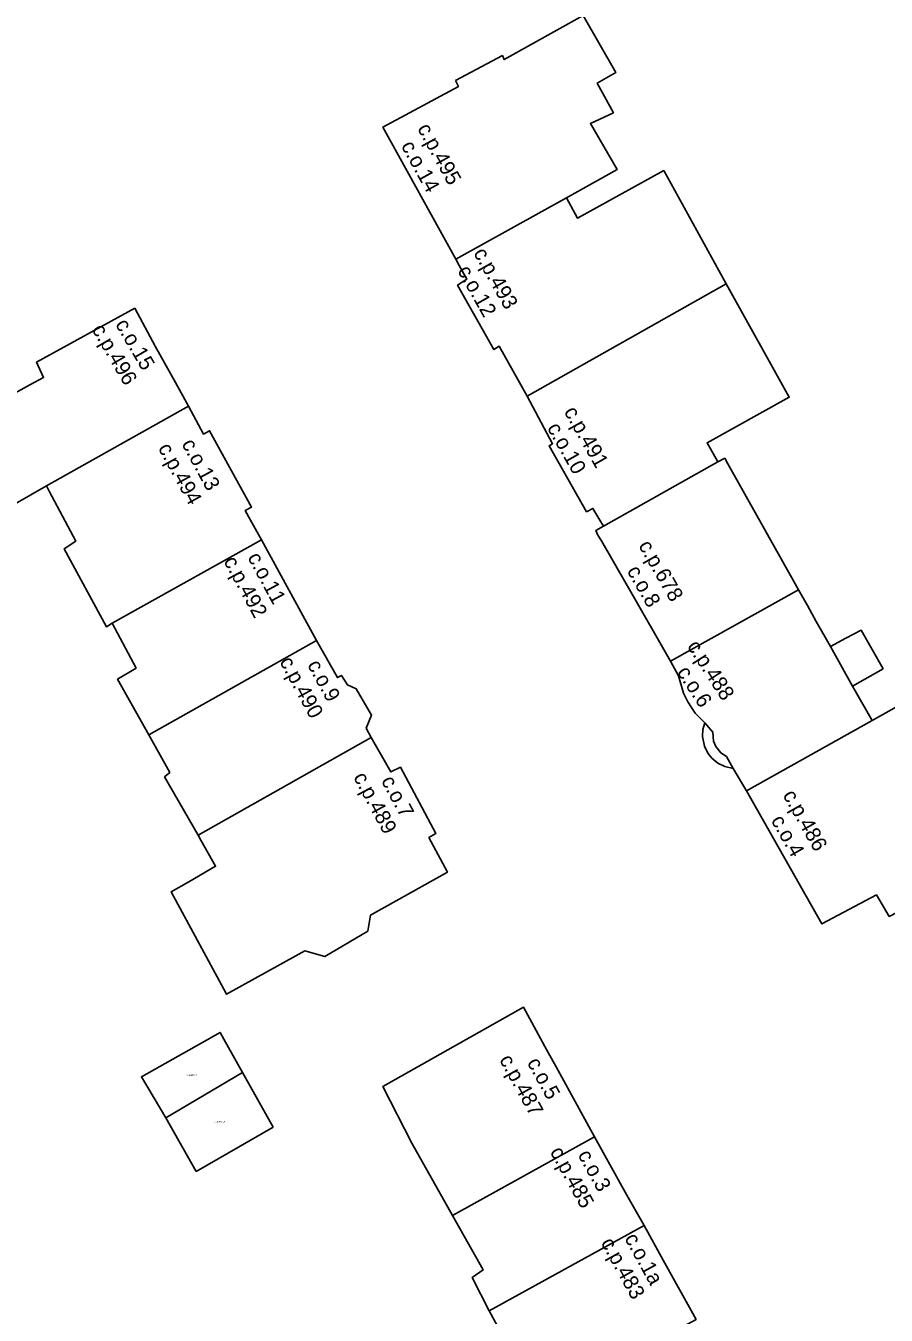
# Model space of a CAD drawing. Extents: x -600391 to -599491, y -1160176 to -1159402.
# Drawn here: x -600213.3 to -600156.5, y -1160026.2 to -1159941 of the extents above; entities that cross this region are included whole.
import ezdxf

# ---------------------------------------------------------------- set-up
doc = ezdxf.new("R2010")
doc.units = 0
for name, color, linetype in [('Level 10', 7, 'Continuous'), ('Level 12', 7, 'Continuous'), ('Level 25', 7, 'Continuous'), ('Level 61', 7, 'Continuous'), ('Level 62', 7, 'Continuous')]:
    doc.layers.add(name, color=color, linetype=linetype)

msp = doc.modelspace()

# ---------------------------------------------------------------- linework, layer by layer
at = {"layer": 'Level 61'}
for points in [[(-600181.7, -1159943.27), (-600176.48, -1159940.35)], [(-600176.48, -1159940.35), (-600174.33, -1159944.13)], [(-600184.92, -1159944.66), (-600181.82, -1159943.01)], [(-600181.82, -1159943.01), (-600181.7, -1159943.27)], [(-600184.72, -1159945.04), (-600184.92, -1159944.66)], [(-600174.33, -1159944.13), (-600175.55, -1159944.82)], [(-600189.71, -1159947.73), (-600184.72, -1159945.04)], [(-600175.55, -1159944.82), (-600174.49, -1159946.78)], [(-600174.49, -1159946.78), (-600176.01, -1159947.5)], [(-600184.9, -1159956.46), (-600189.71, -1159947.73)], [(-600176.01, -1159947.5), (-600174.24, -1159950.54)], [(-600174.24, -1159950.54), (-600177.59, -1159952.4)], [(-600176.86, -1159953.74), (-600171.16, -1159950.6)], [(-600171.16, -1159950.6), (-600167.05, -1159958.08)], [(-600177.59, -1159952.4), (-600184.9, -1159956.46)], [(-600184.9, -1159956.46), (-600177.59, -1159952.4)], [(-600177.59, -1159952.4), (-600176.86, -1159953.74)], [(-600184.67, -1159956.87), (-600184.9, -1159956.46)], [(-600184.17, -1159957.78), (-600184.67, -1159956.87)], [(-600184.78, -1159958.16), (-600184.17, -1159957.78)], [(-600182.38, -1159962.42), (-600184.78, -1159958.16)], [(-600167.05, -1159958.08), (-600180.17, -1159965.49)], [(-600180.17, -1159965.49), (-600167.05, -1159958.08)], [(-600167.05, -1159958.08), (-600162.88, -1159965.57)], [(-600212.57, -1159963.25), (-600206.09, -1159959.69)], [(-600206.09, -1159959.69), (-600204.75, -1159962.19)], [(-600204.75, -1159962.19), (-600203.41, -1159964.59)], [(-600182.03, -1159962.2), (-600182.38, -1159962.42)], [(-600180.17, -1159965.49), (-600182.03, -1159962.2)], [(-600212.11, -1159964.26), (-600212.57, -1159963.25)], [(-600213.02, -1159964.76), (-600212.11, -1159964.26)], [(-600215.57, -1159966.17), (-600213.02, -1159964.76)], [(-600203.41, -1159964.59), (-600202.55, -1159966.16)], [(-600178.5, -1159968.64), (-600180.17, -1159965.49)], [(-600162.88, -1159965.57), (-600168.3, -1159968.58)], [(-600211.91, -1159971.43), (-600202.55, -1159966.16)], [(-600202.55, -1159966.16), (-600211.91, -1159971.43)], [(-600202.55, -1159966.16), (-600201.55, -1159968)], [(-600201.55, -1159968), (-600201.15, -1159967.78)], [(-600201.15, -1159967.78), (-600198.39, -1159972.83)], [(-600178.73, -1159968.77), (-600178.5, -1159968.64)], [(-600168.3, -1159968.58), (-600167.59, -1159969.84)], [(-600176.26, -1159973.13), (-600178.73, -1159968.77)], [(-600175.15, -1159974.08), (-600167.59, -1159969.84)], [(-600167.59, -1159969.84), (-600175.15, -1159974.08)], [(-600167.59, -1159969.84), (-600167.14, -1159969.6)], [(-600167.14, -1159969.6), (-600166.94, -1159969.96)], [(-600166.94, -1159969.96), (-600162.6, -1159977.69)], [(-600211.91, -1159971.43), (-600213.99, -1159972.6)], [(-600211.73, -1159971.78), (-600211.91, -1159971.43)], [(-600209.99, -1159975.07), (-600211.73, -1159971.78)], [(-600198.39, -1159972.83), (-600198.79, -1159973.05)], [(-600198.79, -1159973.05), (-600198.44, -1159973.69)], [(-600198.44, -1159973.69), (-600197.72, -1159974.99)], [(-600175.84, -1159972.91), (-600176.26, -1159973.13)], [(-600175.39, -1159973.68), (-600175.84, -1159972.91)], [(-600175.15, -1159974.08), (-600175.39, -1159973.68)], [(-600175.65, -1159974.37), (-600175.15, -1159974.08)], [(-600175.51, -1159974.68), (-600175.65, -1159974.37)], [(-600210.75, -1159975.58), (-600209.99, -1159975.07)], [(-600197.72, -1159974.99), (-600207.58, -1159980.5)], [(-600207.58, -1159980.5), (-600197.72, -1159974.99)], [(-600197.72, -1159974.99), (-600194.09, -1159981.64)], [(-600175.27, -1159975.05), (-600175.51, -1159974.68)], [(-600173.64, -1159977.9), (-600175.27, -1159975.05)], [(-600207.96, -1159980.73), (-600210.75, -1159975.58)], [(-600173.42, -1159978.27), (-600173.64, -1159977.9)], [(-600162.6, -1159977.69), (-600162.26, -1159978.29)], [(-600170.72, -1159982.99), (-600173.42, -1159978.27)], [(-600170.72, -1159982.99), (-600162.26, -1159978.29)], [(-600162.26, -1159978.29), (-600170.72, -1159982.99)], [(-600162.26, -1159978.29), (-600161.68, -1159979.33)], [(-600161.68, -1159979.33), (-600161.09, -1159980.38)], [(-600207.58, -1159980.5), (-600207.96, -1159980.73)], [(-600206, -1159983.45), (-600207.58, -1159980.5)], [(-600161.09, -1159980.38), (-600160.15, -1159982.04)], [(-600159.13, -1159981.49), (-600158.13, -1159980.95)], [(-600158.13, -1159980.95), (-600156.68, -1159983.5)], [(-600205.17, -1159987.86), (-600194.09, -1159981.64)], [(-600194.09, -1159981.64), (-600205.17, -1159987.86)], [(-600194.09, -1159981.64), (-600192.71, -1159984.08)], [(-600160.15, -1159982.04), (-600159.13, -1159981.49)], [(-600158.7, -1159984.64), (-600160.15, -1159982.04)], [(-600160.15, -1159982.04), (-600158.7, -1159984.64)], [(-600170.18, -1159983.97), (-600170.72, -1159982.99)], [(-600207.22, -1159984.19), (-600206, -1159983.45)], [(-600192.71, -1159984.08), (-600192.45, -1159983.94)], [(-600192.45, -1159983.94), (-600192.04, -1159984.57)], [(-600169.85, -1159985.11), (-600170.18, -1159983.97)], [(-600156.68, -1159983.5), (-600158.7, -1159984.64)], [(-600205.17, -1159987.86), (-600207.22, -1159984.19)], [(-600192.04, -1159984.57), (-600191.47, -1159984.83)], [(-600158.7, -1159984.64), (-600157.41, -1159986.92)], [(-600191.47, -1159984.83), (-600190.46, -1159986.56)], [(-600169.57, -1159985.69), (-600169.85, -1159985.11)], [(-600169.09, -1159986.43), (-600169.57, -1159985.69)], [(-600168.45, -1159987.06), (-600169.09, -1159986.43)], [(-600157.41, -1159986.92), (-600155.25, -1159985.7)], [(-600190.46, -1159986.56), (-600190.82, -1159987.42)], [(-600168.59, -1159987.52), (-600168.45, -1159987.06)], [(-600167.93, -1159987.69), (-600168.45, -1159987.06)], [(-600168.45, -1159987.06), (-600167.93, -1159987.69)], [(-600157.41, -1159986.92), (-600165.71, -1159991.56)], [(-600165.71, -1159991.56), (-600157.41, -1159986.92)], [(-600203.78, -1159990.35), (-600205.17, -1159987.86)], [(-600190.48, -1159988.03), (-600201.9, -1159994.48)], [(-600201.9, -1159994.48), (-600190.48, -1159988.03)], [(-600190.82, -1159987.42), (-600190.48, -1159988.03)], [(-600190.48, -1159988.03), (-600189.19, -1159990.31)], [(-600168.6, -1159987.98), (-600168.59, -1159987.52)], [(-600168.47, -1159988.62), (-600168.6, -1159987.98)], [(-600167.87, -1159988.29), (-600167.93, -1159987.69)], [(-600167.93, -1159987.69), (-600167.87, -1159988.29)], [(-600168.28, -1159989.03), (-600168.47, -1159988.62)], [(-600168.19, -1159989.16), (-600168.28, -1159989.03)], [(-600167.73, -1159988.64), (-600167.87, -1159988.29)], [(-600167.87, -1159988.29), (-600167.73, -1159988.64)], [(-600167.4, -1159989.06), (-600167.73, -1159988.64)], [(-600167.73, -1159988.64), (-600167.4, -1159989.06)], [(-600167.03, -1159989.3), (-600167.4, -1159989.06)], [(-600167.4, -1159989.06), (-600167.03, -1159989.3)], [(-600167.99, -1159989.4), (-600168.19, -1159989.16)], [(-600167.59, -1159989.73), (-600167.99, -1159989.4)], [(-600167.14, -1159989.95), (-600167.59, -1159989.73)], [(-600166.59, -1159990.08), (-600167.03, -1159989.3)], [(-600167.03, -1159989.3), (-600166.59, -1159990.08)], [(-600204.12, -1159990.64), (-600203.78, -1159990.35)], [(-600201.9, -1159994.48), (-600204.12, -1159990.64)], [(-600189.19, -1159990.31), (-600188.55, -1159990)], [(-600188.55, -1159990), (-600186.21, -1159994.37)], [(-600166.59, -1159990.08), (-600167.14, -1159989.95)], [(-600165.71, -1159991.56), (-600166.59, -1159990.08)], [(-600160.72, -1160000.35), (-600165.71, -1159991.56)], [(-600201.72, -1159994.81), (-600201.9, -1159994.48)], [(-600200.75, -1159996.54), (-600201.72, -1159994.81)], [(-600186.21, -1159994.37), (-600186.67, -1159994.65)], [(-600186.67, -1159994.65), (-600185.45, -1159996.93)], [(-600202.52, -1159997.56), (-600200.75, -1159996.54)], [(-600203.69, -1159998.23), (-600202.52, -1159997.56)], [(-600185.45, -1159996.93), (-600190.52, -1159999.77)], [(-600200.21, -1160004.66), (-600203.69, -1159998.23)], [(-600157.12, -1159998.44), (-600160.72, -1160000.35)], [(-600156.27, -1159999.85), (-600157.12, -1159998.44)], [(-600190.52, -1159999.77), (-600190.71, -1160000.82)], [(-600190.71, -1160000.82), (-600193.54, -1160002.51)], [(-600195.45, -1160002.46), (-600200.03, -1160004.99)], [(-600194.87, -1160002.13), (-600195.45, -1160002.46)], [(-600193.54, -1160002.51), (-600194.87, -1160002.13)], [(-600200.03, -1160004.99), (-600200.21, -1160004.66)], [(-600189.7, -1160011.08), (-600180.43, -1160005.84)], [(-600180.43, -1160005.84), (-600178.89, -1160008.68)], [(-600205.65, -1160010.44), (-600200.46, -1160007.51)], [(-600200.46, -1160007.51), (-600200.2, -1160007.97)], [(-600200.2, -1160007.97), (-600198.98, -1160010.16)], [(-600178.89, -1160008.68), (-600178.27, -1160009.78)], [(-600198.98, -1160010.16), (-600204.03, -1160013.16)], [(-600204.03, -1160013.16), (-600198.98, -1160010.16)], [(-600198.98, -1160010.16), (-600196.94, -1160013.78)], [(-600178.27, -1160009.78), (-600175.73, -1160014.41)], [(-600204.03, -1160013.16), (-600205.65, -1160010.44)], [(-600187.8, -1160014.82), (-600189.7, -1160011.08)], [(-600202.03, -1160016.69), (-600204.03, -1160013.16)], [(-600196.94, -1160013.78), (-600202.03, -1160016.69)], [(-600175.73, -1160014.41), (-600185.12, -1160019.61)], [(-600185.12, -1160019.61), (-600175.73, -1160014.41)], [(-600175.73, -1160014.41), (-600173.6, -1160018.26)], [(-600185.12, -1160019.61), (-600187.8, -1160014.82)], [(-600173.6, -1160018.26), (-600172.45, -1160020.27)], [(-600183.09, -1160023.2), (-600185.12, -1160019.61)], [(-600172.45, -1160020.27), (-600182.69, -1160025.91)], [(-600182.69, -1160025.91), (-600172.45, -1160020.27)], [(-600172.45, -1160020.27), (-600171.2, -1160022.55)], [(-600171.2, -1160022.55), (-600169.03, -1160026.47)], [(-600183.82, -1160023.7), (-600183.09, -1160023.2)], [(-600182.69, -1160025.91), (-600183.82, -1160023.7)], [(-600181.58, -1160027.92), (-600182.69, -1160025.91)]]:
    msp.add_lwpolyline(points, dxfattribs=at)
at = {"layer": 'Level 62'}
for points in [[(-600184.92, -1159944.66), (-600181.82, -1159943.01), (-600181.7, -1159943.27), (-600176.48, -1159940.35), (-600174.33, -1159944.13), (-600175.55, -1159944.82), (-600174.49, -1159946.78), (-600176.01, -1159947.5), (-600174.24, -1159950.54), (-600177.59, -1159952.4), (-600184.9, -1159956.46), (-600189.71, -1159947.73), (-600184.72, -1159945.04), (-600184.92, -1159944.66)], [(-600184.67, -1159956.87), (-600184.9, -1159956.46), (-600177.59, -1159952.4), (-600176.86, -1159953.74), (-600171.16, -1159950.6), (-600167.05, -1159958.08), (-600180.17, -1159965.49), (-600182.03, -1159962.2), (-600182.38, -1159962.42), (-600184.78, -1159958.16), (-600184.17, -1159957.78), (-600184.67, -1159956.87)], [(-600180.17, -1159965.49), (-600167.05, -1159958.08), (-600162.88, -1159965.57), (-600168.3, -1159968.58), (-600167.59, -1159969.84), (-600175.15, -1159974.08), (-600175.39, -1159973.68), (-600175.84, -1159972.91), (-600176.26, -1159973.13), (-600178.73, -1159968.77), (-600178.5, -1159968.64), (-600180.17, -1159965.49)], [(-600206.09, -1159959.69), (-600204.75, -1159962.19), (-600203.41, -1159964.59), (-600202.55, -1159966.16), (-600211.91, -1159971.43), (-600213.99, -1159972.6), (-600214.55, -1159971.59), (-600215.04, -1159970.72), (-600216.94, -1159967.32), (-600215.4, -1159966.42), (-600215.57, -1159966.17), (-600213.02, -1159964.76), (-600212.11, -1159964.26), (-600212.57, -1159963.25), (-600206.09, -1159959.69)], [(-600202.55, -1159966.16), (-600201.55, -1159968), (-600201.15, -1159967.78), (-600198.39, -1159972.83), (-600198.79, -1159973.05), (-600198.44, -1159973.69), (-600197.72, -1159974.99), (-600207.58, -1159980.5), (-600207.96, -1159980.73), (-600210.75, -1159975.58), (-600209.99, -1159975.07), (-600211.73, -1159971.78), (-600211.91, -1159971.43), (-600202.55, -1159966.16)], [(-600162.6, -1159977.69), (-600162.26, -1159978.29), (-600170.72, -1159982.99), (-600173.42, -1159978.27), (-600173.64, -1159977.9), (-600175.27, -1159975.05), (-600175.51, -1159974.68), (-600175.65, -1159974.37), (-600175.15, -1159974.08), (-600167.59, -1159969.84), (-600167.14, -1159969.6), (-600166.94, -1159969.96), (-600162.6, -1159977.69)], [(-600207.58, -1159980.5), (-600197.72, -1159974.99), (-600194.09, -1159981.64), (-600205.17, -1159987.86), (-600207.22, -1159984.19), (-600206, -1159983.45), (-600207.58, -1159980.5)], [(-600165.71, -1159991.56), (-600166.59, -1159990.08), (-600167.03, -1159989.3), (-600167.4, -1159989.06), (-600167.73, -1159988.64), (-600167.87, -1159988.29), (-600167.93, -1159987.69), (-600168.45, -1159987.06), (-600169.09, -1159986.43), (-600169.57, -1159985.69), (-600169.85, -1159985.11), (-600170.18, -1159983.97), (-600170.72, -1159982.99), (-600162.26, -1159978.29), (-600161.68, -1159979.33), (-600161.09, -1159980.38), (-600160.15, -1159982.04), (-600158.7, -1159984.64), (-600157.41, -1159986.92), (-600165.71, -1159991.56)], [(-600160.15, -1159982.04), (-600159.13, -1159981.49), (-600158.13, -1159980.95), (-600156.68, -1159983.5), (-600158.7, -1159984.64), (-600160.15, -1159982.04)], [(-600201.9, -1159994.48), (-600204.12, -1159990.64), (-600203.78, -1159990.35), (-600205.17, -1159987.86), (-600194.09, -1159981.64), (-600192.71, -1159984.08), (-600192.45, -1159983.94), (-600192.04, -1159984.57), (-600191.47, -1159984.83), (-600190.46, -1159986.56), (-600190.82, -1159987.42), (-600190.48, -1159988.03), (-600201.9, -1159994.48)], [(-600165.71, -1159991.56), (-600157.41, -1159986.92), (-600155.25, -1159985.7), (-600154.23, -1159987.5), (-600153.94, -1159987.28), (-600153.58, -1159987.13), (-600153.2, -1159987.08), (-600153.13, -1159987.08), (-600152.87, -1159987.11), (-600152.57, -1159987.2), (-600152.26, -1159987.37), (-600152.05, -1159987.56), (-600148.58, -1159993.72), (-600154.48, -1159996.99), (-600153.7, -1159998.51), (-600156.27, -1159999.85), (-600157.12, -1159998.44), (-600160.72, -1160000.35), (-600165.71, -1159991.56)], [(-600168.45, -1159987.06), (-600167.93, -1159987.69), (-600167.87, -1159988.29), (-600167.73, -1159988.64), (-600167.4, -1159989.06), (-600167.03, -1159989.3), (-600166.59, -1159990.08), (-600167.14, -1159989.95), (-600167.59, -1159989.73), (-600167.99, -1159989.4), (-600168.19, -1159989.16), (-600168.28, -1159989.03), (-600168.47, -1159988.62), (-600168.6, -1159987.98), (-600168.59, -1159987.52), (-600168.45, -1159987.06)], [(-600201.9, -1159994.48), (-600190.48, -1159988.03), (-600189.19, -1159990.31), (-600188.55, -1159990), (-600186.21, -1159994.37), (-600186.67, -1159994.65), (-600185.45, -1159996.93), (-600190.52, -1159999.77), (-600190.71, -1160000.82), (-600193.54, -1160002.51), (-600194.87, -1160002.13), (-600195.45, -1160002.46), (-600200.03, -1160004.99), (-600200.21, -1160004.66), (-600203.69, -1159998.23), (-600202.52, -1159997.56), (-600200.75, -1159996.54), (-600201.72, -1159994.81), (-600201.9, -1159994.48)], [(-600178.89, -1160008.68), (-600178.27, -1160009.78), (-600175.73, -1160014.41), (-600185.12, -1160019.61), (-600187.8, -1160014.82), (-600189.7, -1160011.08), (-600180.43, -1160005.84), (-600178.89, -1160008.68)], [(-600200.2, -1160007.97), (-600198.98, -1160010.16), (-600204.03, -1160013.16), (-600205.65, -1160010.44), (-600200.46, -1160007.51), (-600200.2, -1160007.97)], [(-600196.94, -1160013.78), (-600202.03, -1160016.69), (-600204.03, -1160013.16), (-600198.98, -1160010.16), (-600196.94, -1160013.78)], [(-600185.12, -1160019.61), (-600175.73, -1160014.41), (-600173.6, -1160018.26), (-600172.45, -1160020.27), (-600182.69, -1160025.91), (-600183.82, -1160023.7), (-600183.09, -1160023.2), (-600185.12, -1160019.61)], [(-600171.2, -1160022.55), (-600169.03, -1160026.47), (-600180.56, -1160032.69), (-600182.88, -1160028.63), (-600181.58, -1160027.92), (-600182.69, -1160025.91), (-600172.45, -1160020.27), (-600171.2, -1160022.55)]]:
    msp.add_lwpolyline(points, dxfattribs=at)

# ---------------------------------------------------------------- texts
at = {"layer": 'Level 10'}
for s, rotation, p in [('c.o.14', 298.84091, (-600188.534, -1159948.962)), ('c.o.12', 299.39521, (-600184.808, -1159957.206)), ('c.o.15', 300.39089, (-600207.405, -1159960.746)), ('c.o.10', 299.53097, (-600178.892, -1159967.588)), ('c.o.13', 298.56153, (-600203.021, -1159968.641)), ('c.o.11', 298.51031, (-600198.672, -1159976.138)), ('c.o.8', 299.81595, (-600173.625, -1159977.029)), ('c.o.9', 298.45133, (-600194.723, -1159983.235)), ('c.o.6', 302.96862, (-600170.325, -1159983.721)), ('c.o.7', 298.16921, (-600189.848, -1159990.887)), ('c.o.4', 299.53097, (-600164.113, -1159993.508)), ('c.o.5', 298.84091, (-600180.217, -1160009.504)), ('c.o.3', 299.00508, (-600176.869, -1160015.595)), ('c.o.1a', 298.90769, (-600173.782, -1160021.105))]:
    msp.add_text(s, height=1, rotation=rotation, dxfattribs=at).set_placement(p)
at = {"layer": 'Level 12'}
for s, rotation, p in [('c.p.495', 298.84091, (-600187.46, -1159947.813)), ('c.p.493', 299.39521, (-600183.756, -1159956.037)), ('c.p.496', 300.39089, (-600208.953, -1159961.088)), ('c.p.491', 299.53097, (-600177.78, -1159966.517)), ('c.p.494', 298.56153, (-600204.577, -1159968.921)), ('c.p.678', 299.81595, (-600172.86, -1159975.36)), ('c.p.492', 298.51031, (-600200.252, -1159976.389)), ('c.p.488', 302.96862, (-600169.655, -1159982.012)), ('c.p.490', 298.45133, (-600196.556, -1159983.019)), ('c.p.489', 298.16921, (-600191.683, -1159990.648)), ('c.p.486', 299.53097, (-600163.336, -1159991.838)), ('c.p.487', 298.84091, (-600182.047, -1160009.309)), ('c.p.485', 299.00508, (-600178.704, -1160015.391)), ('c.p.483', 298.90769, (-600175.344, -1160021.4))]:
    msp.add_text(s, height=1, rotation=rotation, dxfattribs=at).set_placement(p)
at = {"layer": 'Level 25'}
for s, p in [('c.pp.489_A', (-600202.673, -1160010.387)), ('c.pp.487_A', (-600200.823, -1160013.457))]:
    msp.add_text(s, height=0.1, dxfattribs=at).set_placement(p)

doc.saveas('drawing.dxf')
